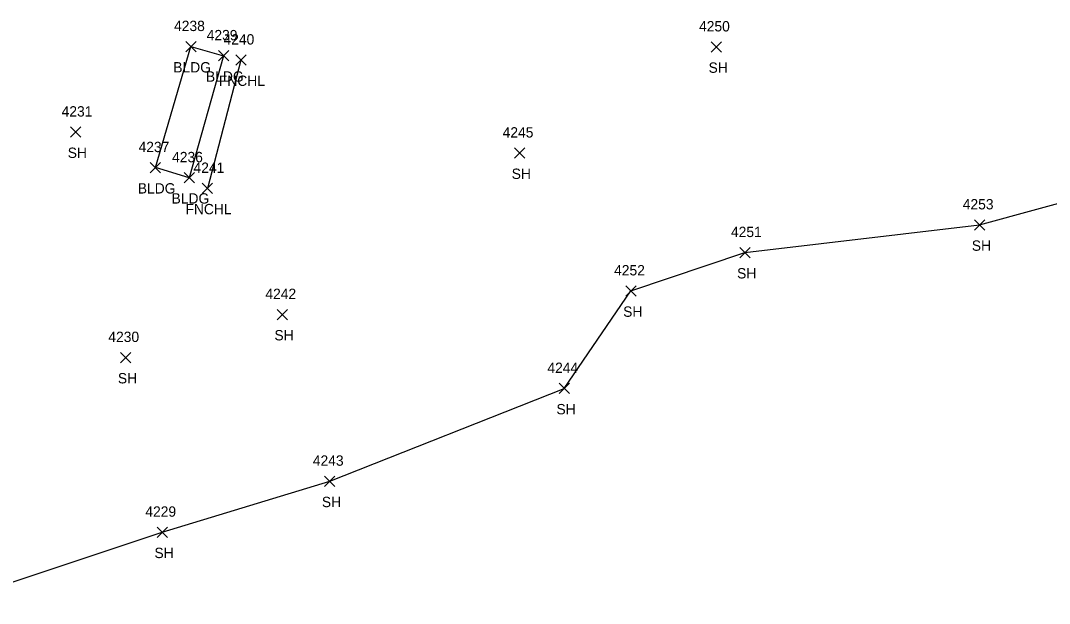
# Model space of a CAD drawing. Extents: x 1509053 to 1511576, y 400838 to 402572.
# Drawn here: x 1510649 to 1510847.9, y 401473.1 to 401585.8 of the extents above; entities that cross this region are included whole.
import ezdxf

# ---------------------------------------------------------------- set-up
doc = ezdxf.new("R2010")
doc.units = 0
for name, color, linetype in [('L_A', 7, 'Continuous'), ('L_I', 7, 'Continuous'), ('L_TIC', 7, 'Continuous'), ('LBC', 7, 'Continuous'), ('LFNC', 7, 'Continuous'), ('LSOGP', 7, 'Continuous')]:
    doc.layers.add(name, color=color, linetype=linetype)

msp = doc.modelspace()

# ---------------------------------------------------------------- linework, layer by layer
at = {"layer": 'L_TIC'}
for points in [[(1510680.96, 401579.76), (1510682.96, 401581.76)], [(1510682.96, 401579.76), (1510680.96, 401581.76)], [(1510782.52, 401579.69), (1510784.52, 401581.69)], [(1510784.52, 401579.69), (1510782.52, 401581.69)], [(1510687.28, 401577.98), (1510689.28, 401579.98)], [(1510689.28, 401577.98), (1510687.28, 401579.98)], [(1510690.61, 401577.16), (1510692.61, 401579.16)], [(1510692.61, 401577.16), (1510690.61, 401579.16)], [(1510658.66, 401563.24), (1510660.66, 401565.24)], [(1510660.66, 401563.24), (1510658.66, 401565.24)], [(1510744.47, 401559.18), (1510746.47, 401561.18)], [(1510746.47, 401559.18), (1510744.47, 401561.18)], [(1510674.1, 401556.36), (1510676.1, 401558.36)], [(1510676.1, 401556.36), (1510674.1, 401558.36)], [(1510680.63, 401554.41), (1510682.63, 401556.41)], [(1510682.63, 401554.41), (1510680.63, 401556.41)], [(1510684.15, 401552.35), (1510686.15, 401554.35)], [(1510686.15, 401552.35), (1510684.15, 401554.35)], [(1510833.4, 401545.29), (1510835.4, 401547.29)], [(1510835.4, 401545.29), (1510833.4, 401547.29)], [(1510788.03, 401539.94), (1510790.03, 401541.94)], [(1510790.03, 401539.94), (1510788.03, 401541.94)], [(1510766.01, 401532.53), (1510768.01, 401534.53)], [(1510768.01, 401532.53), (1510766.01, 401534.53)], [(1510698.61, 401527.97), (1510700.61, 401529.97)], [(1510700.61, 401527.97), (1510698.61, 401529.97)], [(1510668.35, 401519.66), (1510670.35, 401521.66)], [(1510670.35, 401519.66), (1510668.35, 401521.66)], [(1510753.12, 401513.68), (1510755.12, 401515.68)], [(1510755.12, 401513.68), (1510753.12, 401515.68)], [(1510707.78, 401495.74), (1510709.78, 401497.74)], [(1510709.78, 401495.74), (1510707.78, 401497.74)], [(1510675.42, 401485.89), (1510677.42, 401487.89)], [(1510677.42, 401485.89), (1510675.42, 401487.89)]]:
    msp.add_lwpolyline(points, dxfattribs=at)
at = {"layer": 'LBC'}
for points in [[(1510681.63, 401555.41), (1510675.1, 401557.36), (1510681.96, 401580.76), (1510688.28, 401578.98)], [(1510688.28, 401578.98), (1510681.63, 401555.41)]]:
    msp.add_lwpolyline(points, dxfattribs=at)
at = {"layer": 'LFNC'}
msp.add_lwpolyline([(1510691.61, 401578.16), (1510685.15, 401553.35)], dxfattribs=at)
at = {"layer": 'LSOGP'}
msp.add_lwpolyline([(1510634.96, 401473.13), (1510676.42, 401486.89), (1510708.78, 401496.74), (1510754.12, 401514.68), (1510767.01, 401533.53), (1510789.03, 401540.94), (1510834.4, 401546.29), (1510878.7, 401558.4), (1510963.19, 401584.13)], dxfattribs=at)

# ---------------------------------------------------------------- texts
at = {"layer": 'L_A'}
for s, p in [('BLDG', (1510678.55, 401575.76)), ('SH', (1510782.01, 401575.69)), ('BLDG', (1510684.87, 401573.98)), ('FNCHL', (1510687.36, 401573.16)), ('SH', (1510658.15, 401559.24)), ('SH', (1510743.96, 401555.18)), ('BLDG', (1510671.69, 401552.36)), ('BLDG', (1510678.22, 401550.41)), ('FNCHL', (1510680.9, 401548.35)), ('SH', (1510832.89, 401541.29)), ('SH', (1510787.52, 401535.94)), ('SH', (1510765.5, 401528.53)), ('SH', (1510698.1, 401523.97)), ('SH', (1510667.84, 401515.66)), ('SH', (1510752.61, 401509.68)), ('SH', (1510707.27, 401491.74)), ('SH', (1510674.91, 401481.89))]:
    msp.add_text(s, height=2, dxfattribs=at).set_placement(p)
at = {"layer": 'L_I'}
for s, p in [('4238', (1510678.7, 401583.76)), ('4250', (1510780.17, 401583.69)), ('4239', (1510685.01, 401581.98)), ('4240', (1510688.26, 401581.16)), ('4231', (1510656.97, 401567.24)), ('4245', (1510742.21, 401563.18)), ('4237', (1510671.84, 401560.36)), ('4236', (1510678.32, 401558.41)), ('4241', (1510682.46, 401556.35)), ('4253', (1510831.14, 401549.29)), ('4251', (1510786.34, 401543.94)), ('4252', (1510763.75, 401536.53)), ('4242', (1510696.35, 401531.97)), ('4230', (1510666, 401523.66)), ('4244', (1510750.86, 401517.68)), ('4243', (1510705.52, 401499.74)), ('4229', (1510673.15, 401489.89))]:
    msp.add_text(s, height=2, dxfattribs=at).set_placement(p)

doc.saveas('drawing.dxf')
